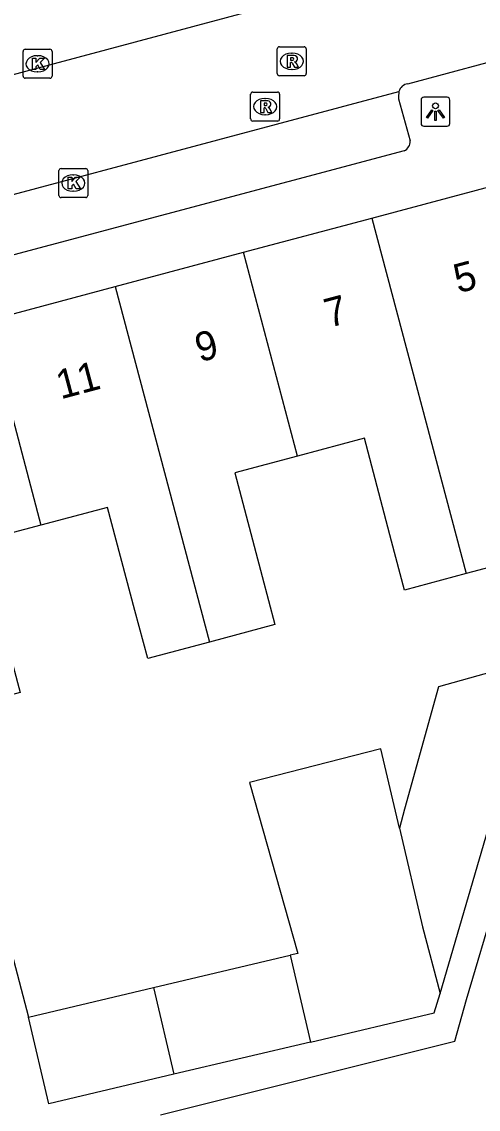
# Model space of a CAD drawing. Extents: x 162542 to 163144, y 380786 to 381511.
# Drawn here: x 163062.26 to 163078.03, y 381101.24 to 381138.75 of the extents above; entities that cross this region are included whole.
import ezdxf

# ---------------------------------------------------------------- set-up
doc = ezdxf.new("R2010")
doc.units = 0
for name, color, linetype in [('IMGEO_Kolk', 7, 'Continuous'), ('IMGEO_Lichtpunt', 7, 'Continuous'), ('IMGEO_Pand', 7, 'Continuous'), ('IMGEO_Pand_nummerreeks', 7, 'Continuous'), ('IMGEO_Rijbaan_lokaal_open', 7, 'Continuous'), ('IMGEO_Rioolput', 7, 'Continuous'), ('IMGEO_Voetpad_open', 7, 'Continuous')]:
    doc.layers.add(name, color=color, linetype=linetype)

msp = doc.modelspace()

# ---------------------------------------------------------------- linework, layer by layer
at = {"layer": 'IMGEO_Kolk'}
for p, q in [((163062.308, 381136.876), (163062.308, 381137.728)), ((163062.383, 381137.802), (163063.235, 381137.802)), ((163062.796, 381137.582), (163062.821, 381137.582)), ((163063.309, 381137.728), (163063.309, 381136.876)), ((163063.235, 381136.802), (163062.383, 381136.802)), ((163062.819, 381137.022), (163062.794, 381137.022)), ((163063.543, 381132.764), (163063.543, 381133.616)), ((163063.618, 381133.69), (163064.47, 381133.69)), ((163064.031, 381133.47), (163064.056, 381133.47)), ((163064.544, 381133.616), (163064.544, 381132.764)), ((163064.47, 381132.69), (163063.618, 381132.69)), ((163064.054, 381132.91), (163064.029, 381132.91))]:
    msp.add_line(p, q, dxfattribs=at)
for points in [[(163062.308, 381136.876), (163062.308, 381137.728)], [(163062.383, 381137.802), (163063.235, 381137.802)], [(163062.629, 381137.502), (163062.752, 381137.502), (163062.752, 381137.351), (163062.882, 381137.502), (163063.046, 381137.502), (163062.9, 381137.351), (163063.053, 381137.102), (163062.901, 381137.102), (163062.816, 381137.266), (163062.752, 381137.199), (163062.752, 381137.102), (163062.629, 381137.102), (163062.629, 381137.502)], [(163063.309, 381137.728), (163063.309, 381136.876)], [(163063.235, 381136.802), (163062.383, 381136.802)], [(163063.543, 381132.764), (163063.543, 381133.616)], [(163063.618, 381133.69), (163064.47, 381133.69)], [(163063.864, 381133.39), (163063.987, 381133.39), (163063.987, 381133.239), (163064.117, 381133.39), (163064.281, 381133.39), (163064.135, 381133.239), (163064.288, 381132.99), (163064.136, 381132.99), (163064.051, 381133.154), (163063.987, 381133.087), (163063.987, 381132.99), (163063.864, 381132.99), (163063.864, 381133.39)], [(163064.544, 381133.616), (163064.544, 381132.764)], [(163064.47, 381132.69), (163063.618, 381132.69)]]:
    msp.add_lwpolyline(points, dxfattribs=at)
for centre, start, end in [((163062.385, 381137.726), 91.552, 178.448), ((163062.385, 381137.726), 91.552, 178.448), ((163063.233, 381137.726), 1.552, 88.448), ((163063.233, 381137.726), 1.552, 88.448), ((163062.385, 381136.878), 181.552, 268.448), ((163062.385, 381136.878), 181.552, 268.448), ((163063.233, 381136.878), 271.552, 358.448), ((163063.233, 381136.878), 271.552, 358.448), ((163063.62, 381133.614), 91.552, 178.448), ((163063.62, 381133.614), 91.552, 178.448), ((163064.468, 381133.614), 1.552, 88.448), ((163064.468, 381133.614), 1.552, 88.448), ((163063.62, 381132.766), 181.552, 268.448), ((163063.62, 381132.766), 181.552, 268.448), ((163064.468, 381132.766), 271.552, 358.448), ((163064.468, 381132.766), 271.552, 358.448)]:
    msp.add_arc(centre, 0.0765, start, end, dxfattribs=at)
for centre, major_axis, ratio, start_param, end_param in [((163062.795, 381137.302), (-0.387, 0.002), 0.722429, 4.712389, 7.853982), ((163062.82, 381137.302), (-0.39, 0.002), 0.717154, 1.570796, 4.712389), ((163064.03, 381133.19), (-0.387, 0.002), 0.722429, 4.712389, 7.853982), ((163064.055, 381133.19), (-0.39, 0.002), 0.717154, 1.570796, 4.712389)]:
    msp.add_ellipse(centre, major_axis=major_axis, ratio=ratio, start_param=start_param, end_param=end_param, dxfattribs=at)
at = {"layer": 'IMGEO_Lichtpunt'}
for p, q in [((163076.05, 381136.053), (163076.05, 381135.246)), ((163076.05, 381136.053), (163076.05, 381135.246)), ((163076.952, 381136.148), (163076.144, 381136.148)), ((163076.952, 381136.148), (163076.144, 381136.148)), ((163077.046, 381135.246), (163077.046, 381136.053)), ((163077.046, 381135.246), (163077.046, 381136.053)), ((163076.144, 381135.152), (163076.952, 381135.152)), ((163076.144, 381135.152), (163076.952, 381135.152))]:
    msp.add_line(p, q, dxfattribs=at)
for points in [[(163076.424, 381135.717), (163076.463, 381135.689), (163076.275, 381135.427), (163076.237, 381135.454), (163076.424, 381135.717)], [(163076.526, 381135.669), (163076.573, 381135.669), (163076.573, 381135.347), (163076.526, 381135.347), (163076.526, 381135.669)], [(163076.636, 381135.689), (163076.674, 381135.716), (163076.861, 381135.454), (163076.822, 381135.426), (163076.636, 381135.689)]]:
    msp.add_lwpolyline(points, dxfattribs=at)
msp.add_circle((163076.549, 381135.851), 0.0994, dxfattribs=at)
for centre, start, end in [((163076.144, 381136.053), 90, 180), ((163076.144, 381136.053), 90, 180), ((163076.952, 381136.053), 0, 90), ((163076.952, 381136.053), 0, 90), ((163076.144, 381135.246), 180, 270), ((163076.144, 381135.246), 180, 270), ((163076.952, 381135.246), 270, 0), ((163076.952, 381135.246), 270, 360)]:
    msp.add_arc(centre, 0.0946, start, end, dxfattribs=at)
at = {"layer": 'IMGEO_Pand'}
for points in [[(163074.352, 381131.982), (163078.785, 381133.164)], [(163069.92, 381130.801), (163074.352, 381131.982)], [(163074.352, 381131.982), (163077.611, 381119.717)], [(163065.487, 381129.619), (163069.92, 381130.801)], [(163071.788, 381123.771), (163069.92, 381130.801)], [(163061.054, 381128.438), (163065.487, 381129.619)], [(163065.487, 381129.619), (163068.746, 381117.355)], [(163061.054, 381128.438), (163062.927, 381121.391)], [(163080.653, 381126.136), (163078.479, 381125.559), (163079.423, 381122.006), (163079.871, 381120.32), (163077.611, 381119.717)], [(163077.611, 381119.717), (163075.483, 381119.15), (163075.034, 381120.84), (163074.093, 381124.383), (163071.788, 381123.771)], [(163071.788, 381123.771), (163069.617, 381123.194), (163070.567, 381119.616), (163071.007, 381117.957), (163068.746, 381117.355)], [(163068.746, 381117.355), (163066.614, 381116.786), (163066.173, 381118.448), (163065.229, 381122.002), (163062.927, 381121.391)], [(163062.927, 381121.391), (163060.827, 381120.833), (163061.776, 381117.26), (163062.213, 381115.613), (163059.881, 381114.992)], [(163078.512, 381116.327), (163076.656, 381115.81), (163075.482, 381111.585), (163075.302, 381110.938)], [(163075.302, 381110.938), (163074.658, 381113.675), (163070.13, 381112.512), (163071.791, 381106.609), (163071.533, 381106.549)], [(163076.714, 381105.235), (163079.044, 381113.224), (163079.318, 381113.292)], [(163075.302, 381110.938), (163076.105, 381107.526), (163076.714, 381105.235)], [(163066.809, 381105.436), (163071.533, 381106.549)], [(163071.533, 381106.549), (163072.237, 381103.556)], [(163062.49, 381104.42), (163066.809, 381105.436)], [(163066.809, 381105.436), (163067.513, 381102.444)], [(163072.237, 381103.556), (163076.507, 381104.562), (163076.714, 381105.235)], [(163067.513, 381102.444), (163063.195, 381101.427), (163062.49, 381104.42)], [(163072.237, 381103.556), (163067.513, 381102.444)]]:
    msp.add_lwpolyline(points, dxfattribs=at)
at = {"layer": 'IMGEO_Rijbaan_lokaal_open'}
for points in [[(163111.367, 381150.145), (163081.377, 381142.115), (163048.005, 381133.196)], [(163075.591, 381136.615), (163082.441, 381138.453)], [(163033.724, 381125.26), (163075.288, 381136.345)]]:
    msp.add_lwpolyline(points, dxfattribs=at)
msp.add_arc((163075.637, 381136.258), 0.36, 97.3736, 166.0341, dxfattribs=at)
at = {"layer": 'IMGEO_Rioolput'}
for p, q in [((163071.161, 381137.888), (163072.013, 381137.888)), ((163071.086, 381136.962), (163071.086, 381137.814)), ((163071.574, 381137.668), (163071.599, 381137.668)), ((163072.087, 381137.814), (163072.087, 381136.962)), ((163072.013, 381136.888), (163071.161, 381136.888)), ((163071.597, 381137.108), (163071.572, 381137.108)), ((163070.167, 381135.4), (163070.167, 381136.252)), ((163070.242, 381136.326), (163071.094, 381136.326)), ((163070.655, 381136.106), (163070.68, 381136.106)), ((163071.168, 381136.252), (163071.168, 381135.4)), ((163071.094, 381135.326), (163070.242, 381135.326)), ((163070.678, 381135.546), (163070.653, 381135.546))]:
    msp.add_line(p, q, dxfattribs=at)
for points in [[(163071.161, 381137.888), (163072.013, 381137.888)], [(163071.086, 381136.962), (163071.086, 381137.814)], [(163071.675, 381137.586), (163071.423, 381137.588), (163071.423, 381137.188)], [(163071.601, 381137.507), (163071.547, 381137.507), (163071.547, 381137.426)], [(163072.087, 381137.814), (163072.087, 381136.962)], [(163071.423, 381137.188), (163071.547, 381137.188), (163071.547, 381137.35), (163071.558, 381137.35)], [(163071.547, 381137.426), (163071.599, 381137.426)], [(163071.605, 381137.321), (163071.676, 381137.188), (163071.816, 381137.188), (163071.751, 381137.314)], [(163072.013, 381136.888), (163071.161, 381136.888)], [(163070.167, 381135.4), (163070.167, 381136.252)], [(163070.242, 381136.326), (163071.094, 381136.326)], [(163070.756, 381136.024), (163070.504, 381136.026), (163070.504, 381135.626)], [(163071.168, 381136.252), (163071.168, 381135.4)], [(163070.504, 381135.626), (163070.628, 381135.626), (163070.628, 381135.788), (163070.639, 381135.788)], [(163070.682, 381135.945), (163070.628, 381135.945), (163070.628, 381135.864)], [(163070.628, 381135.864), (163070.68, 381135.864)], [(163070.686, 381135.759), (163070.757, 381135.626), (163070.897, 381135.626), (163070.832, 381135.752)], [(163071.094, 381135.326), (163070.242, 381135.326)]]:
    msp.add_lwpolyline(points, dxfattribs=at)
for centre, radius, start, end in [((163071.163, 381137.812), 0.0765, 91.552, 178.448), ((163071.163, 381137.812), 0.0765, 91.552, 178.448), ((163072.011, 381137.812), 0.0765, 1.552, 88.448), ((163072.011, 381137.812), 0.0765, 1.552, 88.448), ((163071.607, 381137.411), 0.0964, 77.0061, 93.1865), ((163071.621, 381137.468), 0.0378, 276.6634, 79.6772), ((163071.674, 381137.476), 0.109, 350.3612, 89.416), ((163071.557, 381137.297), 0.0533, 26.0293, 88.6989), ((163071.583, 381137.615), 0.19, 274.7715, 282.9687), ((163071.672, 381137.476), 0.112, 277.5842, 350.9817), ((163071.656, 381137.261), 0.108, 29.5134, 73.7905), ((163071.163, 381136.964), 0.0765, 181.552, 268.448), ((163071.163, 381136.964), 0.0765, 181.552, 268.448), ((163072.011, 381136.964), 0.0765, 271.552, 358.448), ((163072.011, 381136.964), 0.0765, 271.552, 358.448), ((163070.244, 381136.25), 0.0765, 91.552, 178.448), ((163070.244, 381136.25), 0.0765, 91.552, 178.448), ((163070.755, 381135.914), 0.109, 350.3612, 89.416), ((163071.092, 381136.25), 0.0765, 1.552, 88.448), ((163071.092, 381136.25), 0.0765, 1.552, 88.448), ((163070.638, 381135.735), 0.0533, 26.0293, 88.6989), ((163070.664, 381136.053), 0.19, 274.7715, 282.9687), ((163070.688, 381135.849), 0.0964, 77.0061, 93.1865), ((163070.702, 381135.906), 0.0378, 276.6634, 79.6772), ((163070.753, 381135.914), 0.112, 277.5842, 350.9817), ((163070.737, 381135.699), 0.108, 29.5134, 73.7905), ((163070.244, 381135.402), 0.0765, 181.552, 268.448), ((163070.244, 381135.402), 0.0765, 181.552, 268.448), ((163071.092, 381135.402), 0.0765, 271.552, 358.448), ((163071.092, 381135.402), 0.0765, 271.552, 358.448)]:
    msp.add_arc(centre, radius, start, end, dxfattribs=at)
for centre, major_axis, ratio, start_param, end_param in [((163071.573, 381137.388), (-0.387, 0.002), 0.722429, 4.712389, 7.853982), ((163071.598, 381137.388), (-0.39, 0.002), 0.717154, 1.570796, 4.712389), ((163070.654, 381135.826), (-0.387, 0.002), 0.722429, 4.712389, 7.853982), ((163070.679, 381135.826), (-0.39, 0.002), 0.717154, 1.570796, 4.712389)]:
    msp.add_ellipse(centre, major_axis=major_axis, ratio=ratio, start_param=start_param, end_param=end_param, dxfattribs=at)
at = {"layer": 'IMGEO_Voetpad_open'}
for points in [[(163075.278, 381136.093), (163075.678, 381134.64)], [(163075.471, 381134.299), (163034.763, 381123.468)], [(163067.05, 381101.051), (163077.216, 381103.592), (163077.615, 381105.02), (163079.67, 381111.919), (163080.245, 381112.211)], [(163061.127, 381109.598), (163062.49, 381104.42)]]:
    msp.add_lwpolyline(points, dxfattribs=at)
for centre, radius, start, end in [((163076.382, 381136.175), 1.107, 171.1892, 184.2659), ((163075.299, 381134.637), 0.379, 296.9871, 0.4942)]:
    msp.add_arc(centre, radius, start, end, dxfattribs=at)

# ---------------------------------------------------------------- texts
at = {"layer": 'IMGEO_Pand_nummerreeks'}
for s, p in [('5', (163077.331, 381129.381)), ('7', (163072.868, 381128.191)), ('9', (163068.405, 381127.002)), ('11', (163063.607, 381125.724))]:
    msp.add_text(s, height=1, rotation=14.9228, dxfattribs=at).set_placement(p)

doc.saveas('drawing.dxf')
